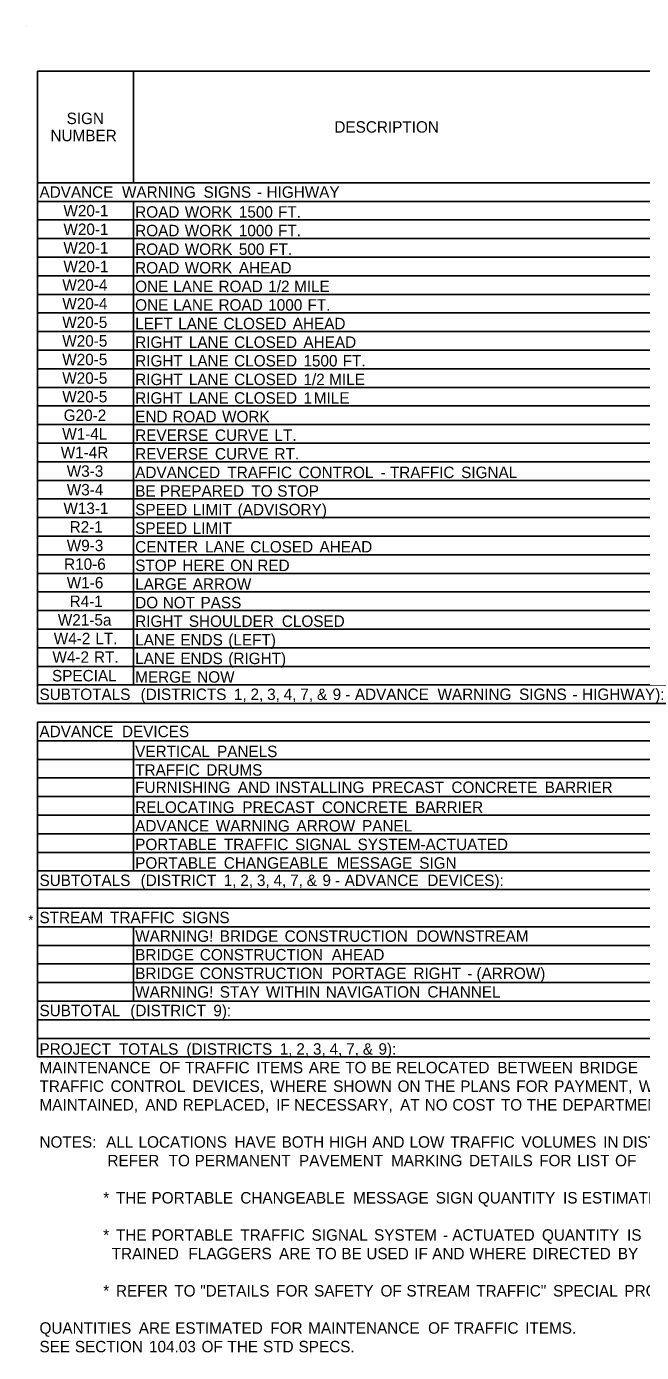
# Model space of a CAD drawing. Extents: x 544255 to 1930787, y -1947044 to 596640.
# Drawn here: x 548277 to 548600, y -1946908 to -1946213 of the extents above; entities that cross this region are included whole.
import ezdxf

# ---------------------------------------------------------------- set-up
doc = ezdxf.new("R2010")
doc.units = 0
doc.layers.add('Default', color=7, linetype='Continuous')

msp = doc.modelspace()

# ---------------------------------------------------------------- linework, layer by layer
at = {"layer": 'Default'}
for p, q in [((548277.5, -1946213.05), (548277.5, -1946213.05)), ((548283.35, -1946236.45), (549393.87, -1946236.45)), ((548283.35, -1946567.95), (548283.35, -1946236.45)), ((548283.35, -1946567.95), (548283.35, -1946236.45)), ((548333.56, -1946294.95), (548333.56, -1946236.45)), ((548283.35, -1946294.95), (549393.87, -1946294.95)), ((548283.35, -1946304.7), (549393.87, -1946304.7)), ((548333.56, -1946558.2), (548333.56, -1946304.7)), ((548333.56, -1946558.2), (548333.56, -1946304.7)), ((548283.35, -1946314.45), (549393.87, -1946314.45)), ((548283.35, -1946324.2), (549393.87, -1946324.2)), ((548283.35, -1946333.95), (549393.87, -1946333.95)), ((548283.35, -1946343.7), (549393.87, -1946343.7)), ((548283.35, -1946353.45), (549393.87, -1946353.45)), ((548283.35, -1946363.2), (549393.87, -1946363.2)), ((548283.35, -1946372.95), (549393.87, -1946372.95)), ((548283.35, -1946382.7), (549393.87, -1946382.7)), ((548283.35, -1946392.45), (549393.87, -1946392.45)), ((548283.35, -1946402.2), (549393.87, -1946402.2)), ((548283.35, -1946411.95), (549393.87, -1946411.95)), ((548283.35, -1946421.7), (549393.87, -1946421.7)), ((548283.35, -1946431.45), (549393.87, -1946431.45)), ((548283.35, -1946441.2), (549393.87, -1946441.2)), ((548283.35, -1946450.95), (549393.87, -1946450.95)), ((548283.35, -1946460.7), (549393.87, -1946460.7)), ((548283.35, -1946470.45), (549393.87, -1946470.45)), ((548283.35, -1946480.2), (549393.87, -1946480.2)), ((548283.35, -1946489.95), (549393.87, -1946489.95)), ((548283.35, -1946499.7), (549393.87, -1946499.7)), ((548283.35, -1946509.45), (549393.87, -1946509.45)), ((548283.35, -1946519.2), (549393.87, -1946519.2)), ((548283.35, -1946528.95), (549393.87, -1946528.95)), ((548283.35, -1946538.7), (549393.87, -1946538.7)), ((548283.35, -1946548.45), (549393.87, -1946548.45)), ((548283.35, -1946558.2), (549393.87, -1946558.2)), ((548283.35, -1946558.2), (549393.87, -1946558.2)), ((548283.35, -1946567.95), (549393.87, -1946567.95)), ((548283.35, -1946577.7), (549393.87, -1946577.7)), ((548283.35, -1946577.7), (549393.87, -1946577.7)), ((548283.35, -1946753.2), (548283.35, -1946577.7)), ((548283.35, -1946753.2), (548283.35, -1946577.7)), ((548283.35, -1946587.45), (549393.87, -1946587.45)), ((548333.56, -1946606.95), (548333.56, -1946587.45)), ((548333.56, -1946655.7), (548333.56, -1946587.45)), ((548283.35, -1946597.2), (549393.87, -1946597.2)), ((548283.35, -1946606.95), (549393.87, -1946606.95)), ((548283.35, -1946616.7), (548333.56, -1946616.7)), ((548283.35, -1946616.7), (549393.87, -1946616.7)), ((548333.56, -1946655.7), (548333.56, -1946616.7)), ((548283.35, -1946626.45), (549393.87, -1946626.45)), ((548283.35, -1946636.2), (549393.87, -1946636.2)), ((548283.35, -1946645.95), (549393.87, -1946645.95)), ((548283.35, -1946655.7), (548809.85, -1946655.7)), ((548283.35, -1946655.7), (549393.87, -1946655.7)), ((548283.35, -1946665.45), (549393.87, -1946665.45)), ((548283.35, -1946675.2), (549393.87, -1946675.2)), ((548283.35, -1946684.95), (549393.87, -1946684.95)), ((548333.56, -1946723.95), (548333.56, -1946684.95)), ((548283.35, -1946694.7), (549393.87, -1946694.7)), ((548283.35, -1946704.45), (549393.87, -1946704.45)), ((548283.35, -1946714.2), (549393.87, -1946714.2)), ((548283.35, -1946723.95), (549393.87, -1946723.95)), ((548283.35, -1946733.7), (549393.87, -1946733.7)), ((548283.35, -1946743.45), (549393.87, -1946743.45)), ((548283.35, -1946753.2), (549393.87, -1946753.2))]:
    msp.add_line(p, q, dxfattribs=at)

# ---------------------------------------------------------------- texts
for s, height, p in [('SIGN', 6, (548298.54, -1946264.2)), ('DESCRIPTION', 6, (548439.07, -1946268.7)), ('NUMBER', 6, (548290.08, -1946273.2)), ('ADVANCE', 6, (548284.32, -1946302.83)), (' WARNING', 6, (548325.37, -1946302.83)), (' SIGNS', 6, (548368.17, -1946302.83)), (' HIGHWAY', 6, (548401.23, -1946302.83)), ('W20-1', 6, (548296.89, -1946312.58)), (' -', 6, (548396.17, -1946302.83)), ('ROAD', 6, (548334.54, -1946313.25)), (' WORK', 6, (548358.31, -1946313.25)), (' 1500', 6, (548386.7, -1946313.25)), (' FT.', 6, (548407.27, -1946313.25)), ('W20-1', 6, (548296.89, -1946322.33)), ('ROAD', 6, (548334.54, -1946323)), (' WORK', 6, (548358.31, -1946323)), (' 1000', 6, (548386.7, -1946323)), (' FT.', 6, (548407.27, -1946323)), ('W20-1', 6, (548296.89, -1946332.08)), ('ROAD', 6, (548334.54, -1946332.75)), (' WORK', 6, (548358.31, -1946332.75)), (' 500', 6, (548386.7, -1946332.75)), (' FT.', 6, (548402.61, -1946332.75)), ('W20-1', 6, (548296.89, -1946341.83)), ('ROAD', 6, (548334.54, -1946342.5)), (' WORK', 6, (548358.31, -1946342.5)), (' AHEAD', 6, (548386.7, -1946342.5)), ('W20-4', 6, (548296.32, -1946351.58)), ('ONE', 6, (548334.54, -1946352.25)), (' LANE', 6, (548352.26, -1946352.25)), (' ROAD', 6, (548376.04, -1946352.25)), (' 1/2', 6, (548402.14, -1946352.25)), (' MILE', 6, (548415.67, -1946352.25)), ('W20-4', 6, (548296.32, -1946361.33)), ('ONE', 6, (548334.54, -1946362)), (' LANE', 6, (548352.26, -1946362)), (' ROAD', 6, (548376.04, -1946362)), (' 1000', 6, (548402.14, -1946362)), (' FT.', 6, (548422.71, -1946362)), ('W20-5', 6, (548296.28, -1946371.08)), ('LEFT', 6, (548334.54, -1946371.75)), (' LANE', 6, (548354.86, -1946371.75)), (' CLOSED', 6, (548378.64, -1946371.75)), (' AHEAD', 6, (548415, -1946371.75)), ('W20-5', 6, (548296.28, -1946380.83)), ('RIGHT', 6, (548334.54, -1946381.5)), (' LANE', 6, (548360.45, -1946381.5)), (' CLOSED', 6, (548384.23, -1946381.5)), (' AHEAD', 6, (548420.59, -1946381.5)), ('W20-5', 6, (548296.28, -1946390.58)), ('RIGHT', 6, (548334.54, -1946391.25)), (' LANE', 6, (548360.45, -1946391.25)), (' CLOSED', 6, (548384.23, -1946391.25)), (' 1500', 6, (548420.59, -1946391.25)), (' FT.', 6, (548441.15, -1946391.25)), ('W20-5', 6, (548296.28, -1946400.33)), ('RIGHT', 6, (548334.54, -1946401)), (' LANE', 6, (548360.45, -1946401)), (' CLOSED', 6, (548384.23, -1946401)), (' 1/2', 6, (548420.59, -1946401)), (' MILE', 6, (548434.12, -1946401)), ('W20-5', 6, (548296.28, -1946410.08)), ('RIGHT', 6, (548334.54, -1946410.75)), (' LANE', 6, (548360.45, -1946410.75)), (' CLOSED', 6, (548384.23, -1946410.75)), (' 1', 6, (548420.59, -1946410.75)), (' MILE', 6, (548426.03, -1946410.75)), ('G20-2', 6, (548297.03, -1946419.83)), ('END', 6, (548334.54, -1946420.5)), (' ROAD', 6, (548351.79, -1946420.5)), (' WORK', 6, (548377.89, -1946420.5)), ('W1-4L', 6, (548296.26, -1946429.58)), ('REVERSE', 6, (548334.54, -1946430.25)), (' CURVE', 6, (548374.16, -1946430.25)), (' LT.', 6, (548405.39, -1946430.25)), ('W1-4R', 6, (548295.47, -1946439.33)), ('REVERSE', 6, (548334.54, -1946440)), (' CURVE', 6, (548374.16, -1946440)), (' RT.', 6, (548405.39, -1946440)), ('W3-3', 6, (548298.63, -1946449.08)), ('ADVANCED', 6, (548334.54, -1946449.75)), (' TRAFFIC', 6, (548380.68, -1946449.75)), (' CONTROL', 6, (548418.07, -1946449.75)), (' TRAFFIC', 6, (548465.95, -1946449.75)), (' SIGNAL', 6, (548503.34, -1946449.75)), ('W3-4', 6, (548298.65, -1946458.83)), (' -', 6, (548461.09, -1946449.75)), ('BE', 6, (548334.54, -1946459.5)), (' PREPARED', 6, (548345.27, -1946459.5)), (' TO', 6, (548393.28, -1946459.5)), (' STOP', 6, (548406.88, -1946459.5)), ('W13-1', 6, (548296.89, -1946468.58)), ('SPEED', 6, (548334.54, -1946469.25)), (' LIMIT', 6, (548362.52, -1946469.25)), (' (ADVISORY)', 6, (548386.09, -1946469.25)), ('R2-1', 6, (548300.14, -1946478.33)), ('SPEED', 6, (548334.54, -1946479)), (' LIMIT', 6, (548362.52, -1946479)), ('W9-3', 6, (548298.63, -1946488.08)), ('CENTER', 6, (548334.54, -1946488.75)), (' LANE', 6, (548368.89, -1946488.75)), (' CLOSED', 6, (548392.68, -1946488.75)), (' AHEAD', 6, (548429.03, -1946488.75)), ('R10-6', 6, (548297.23, -1946497.83)), ('STOP', 6, (548334.54, -1946498.5)), (' HERE', 6, (548357, -1946498.5)), (' ON', 6, (548382.18, -1946498.5)), (' RED', 6, (548396.39, -1946498.5)), ('W1-6', 6, (548298.63, -1946507.58)), ('LARGE', 6, (548334.54, -1946508.25)), (' ARROW', 6, (548362.51, -1946508.25)), ('R4-1', 6, (548300.14, -1946517.33)), ('DO', 6, (548334.54, -1946518)), (' NOT', 6, (548346.74, -1946518)), (' PASS', 6, (548366.59, -1946518)), ('W21-5a', 6, (548293.96, -1946527.08)), ('RIGHT', 6, (548334.54, -1946527.75)), (' SHOULDER', 6, (548360.45, -1946527.75)), (' CLOSED', 6, (548409.25, -1946527.75)), ('W4-2', 6, (548291.81, -1946536.83)), (' LT.', 6, (548311.39, -1946536.83)), ('LANE', 6, (548334.54, -1946537.5)), (' ENDS', 6, (548355.99, -1946537.5)), (' (LEFT)', 6, (548381.17, -1946537.5)), ('W4-2', 6, (548291.12, -1946546.58)), (' RT.', 6, (548310.69, -1946546.58)), ('LANE', 6, (548334.54, -1946547.25)), (' ENDS', 6, (548355.99, -1946547.25)), (' (RIGHT)', 6, (548381.17, -1946547.25)), ('SPECIAL', 6, (548290.9, -1946556.33)), ('MERGE', 6, (548334.54, -1946557)), (' NOW', 6, (548364.83, -1946557)), ('SUBTOTALS', 6, (548284.32, -1946566.08)), (' (DISTRICTS', 6, (548335.15, -1946566.08)), (' 1,', 6, (548384.11, -1946566.08)), (' 2,', 6, (548392.82, -1946566.08)), (' 3,', 6, (548401.53, -1946566.08)), (' 4,', 6, (548410.24, -1946566.08)), (' 7,', 6, (548418.95, -1946566.08)), (' &', 6, (548427.67, -1946566.08)), (' 9', 6, (548435.91, -1946566.08)), (' -', 6, (548442.51, -1946566.08)), (' ADVANCE', 6, (548447.57, -1946566.08)), (' WARNING', 6, (548490.94, -1946566.08)), (' SIGNS', 6, (548533.74, -1946566.08)), (' -', 6, (548561.75, -1946566.08)), (' HIGHWAY):', 6, (548566.8, -1946566.08)), ('ADVANCE', 6, (548284.32, -1946585.58)), (' DEVICES', 6, (548325.37, -1946585.58)), ('VERTICAL', 6, (548334.54, -1946596)), (' PANELS', 6, (548375.24, -1946596)), ('TRAFFIC', 6, (548334.54, -1946605.75)), (' DRUMS', 6, (548369.6, -1946605.75)), ('FURNISHING', 6, (548334.54, -1946614.83)), (' AND', 6, (548386.18, -1946614.83)), (' INSTALLING', 6, (548405.76, -1946614.83)), (' PRECAST', 6, (548456.48, -1946614.83)), (' CONCRETE', 6, (548498.24, -1946614.83)), (' BARRIER', 6, (548547.17, -1946614.83)), ('RELOCATING', 6, (548334.54, -1946625.25)), (' PRECAST', 6, (548388.51, -1946625.25)), (' CONCRETE', 6, (548430.28, -1946625.25)), (' BARRIER', 6, (548479.2, -1946625.25)), ('ADVANCE', 6, (548334.54, -1946635)), (' WARNING', 6, (548374.63, -1946635)), (' ARROW', 6, (548416.95, -1946635)), (' PANEL', 6, (548451.31, -1946635)), ('PORTABLE', 6, (548334.54, -1946644.75)), (' TRAFFIC', 6, (548378.82, -1946644.75)), (' SIGNAL', 6, (548416.21, -1946644.75)), (' SYSTEM-ACTUATED', 6, (548448.99, -1946644.75)), ('PORTABLE', 6, (548334.54, -1946654.5)), (' CHANGEABLE', 6, (548378.82, -1946654.5)), (' MESSAGE', 6, (548438.01, -1946654.5)), (' SIGN', 6, (548481.36, -1946654.5)), ('SUBTOTALS', 6, (548284.32, -1946663.58)), (' (DISTRICT', 6, (548335.15, -1946663.58)), (' 1,', 6, (548378.75, -1946663.58)), (' 2,', 6, (548387.46, -1946663.58)), (' 3,', 6, (548396.17, -1946663.58)), (' 4,', 6, (548404.89, -1946663.58)), (' 7,', 6, (548413.6, -1946663.58)), (' &', 6, (548422.31, -1946663.58)), (' 9', 6, (548430.56, -1946663.58)), (' -', 6, (548437.15, -1946663.58)), (' ADVANCE', 6, (548442.21, -1946663.58)), (' DEVICES):', 6, (548485.58, -1946663.58)), ('*', 5, (548278.47, -1946683.95)), ('STREAM', 6, (548284.32, -1946683.08)), (' TRAFFIC', 6, (548319.13, -1946683.08)), (' SIGNS', 6, (548356.88, -1946683.08)), ('WARNING!', 6, (548334.54, -1946692.83)), (' BRIDGE', 6, (548376.69, -1946692.83)), (' CONSTRUCTION', 6, (548410.72, -1946692.83)), (' DOWNSTREAM', 6, (548479.89, -1946692.83)), ('BRIDGE', 6, (548334.54, -1946702.58)), (' CONSTRUCTION', 6, (548366.23, -1946702.58)), (' AHEAD', 6, (548435.41, -1946702.58)), ('BRIDGE', 6, (548334.54, -1946712.33)), (' CONSTRUCTION', 6, (548366.23, -1946712.33)), (' PORTAGE', 6, (548435.41, -1946712.33)), (' RIGHT', 6, (548478.29, -1946712.33)), (' -', 6, (548506.53, -1946712.33)), (' (ARROW)', 6, (548511.39, -1946712.33)), ('WARNING!', 6, (548334.54, -1946722.08)), (' STAY', 6, (548376.69, -1946722.08)), (' WITHIN', 6, (548400.86, -1946722.08)), (' NAVIGATION', 6, (548432.3, -1946722.08)), (' CHANNEL', 6, (548485.65, -1946722.08)), ('SUBTOTAL', 6, (548284.32, -1946731.83)), (' (DISTRICT', 6, (548329.72, -1946731.83)), (' 9):', 6, (548373.32, -1946731.83)), ('PROJECT', 6, (548284.32, -1946752)), (' TOTALS', 6, (548323.75, -1946752)), (' (DISTRICTS', 6, (548359.2, -1946752)), (' 1,', 6, (548408.16, -1946752)), (' 2,', 6, (548416.87, -1946752)), (' 3,', 6, (548425.58, -1946752)), (' 4,', 6, (548434.29, -1946752)), (' 7,', 6, (548443, -1946752)), (' &', 6, (548451.72, -1946752)), (' 9):', 6, (548459.96, -1946752)), ('MAINTENANCE', 6, (548284.32, -1946761.75)), (' OF', 6, (548344.9, -1946761.75)), (' TRAFFIC', 6, (548358.49, -1946761.75)), (' ITEMS', 6, (548395.88, -1946761.75)), (' ARE', 6, (548423.39, -1946761.75)), (' TO', 6, (548442.51, -1946761.75)), (' BE', 6, (548456.1, -1946761.75)), (' RELOCATED', 6, (548469.17, -1946761.75)), (' BETWEEN', 6, (548522.29, -1946761.75)), (' BRIDGE', 6, (548565.4, -1946761.75)), ('TRAFFIC', 6, (548284.32, -1946771.5)), (' CONTROL', 6, (548319.39, -1946771.5)), (' DEVICES,', 6, (548362.41, -1946771.5)), (' WHERE', 6, (548403.13, -1946771.5)), (' SHOWN', 6, (548436.21, -1946771.5)), (' ON', 6, (548469.99, -1946771.5)), (' THE', 6, (548484.21, -1946771.5)), (' PLANS', 6, (548502.86, -1946771.5)), (' FOR', 6, (548532.24, -1946771.5)), (' PAYMENT,', 6, (548552.15, -1946771.5)), (' WILL', 6, (548596.59, -1946771.5)), ('MAINTAINED,', 6, (548284.32, -1946781.25)), (' AND', 6, (548337.61, -1946781.25)), (' REPLACED,', 6, (548357.19, -1946781.25)), (' IF', 6, (548406.3, -1946781.25)), (' NECESSARY,', 6, (548415.69, -1946781.25)), (' AT', 6, (548471.33, -1946781.25)), (' NO', 6, (548484.2, -1946781.25)), (' COST', 6, (548498.73, -1946781.25)), (' TO', 6, (548524.18, -1946781.25)), (' THE', 6, (548537.77, -1946781.25)), (' DEPARTMENT.', 6, (548556.42, -1946781.25)), ('NOTES:', 6, (548284.32, -1946800.75)), ('  ALL', 6, (548314.8, -1946800.75)), (' LOCATIONS', 6, (548334.08, -1946800.75)), (' HAVE', 6, (548384.41, -1946800.75)), (' BOTH', 6, (548409.13, -1946800.75)), (' HIGH', 6, (548434.07, -1946800.75)), (' AND', 6, (548456.68, -1946800.75)), (' LOW', 6, (548476.26, -1946800.75)), (' TRAFFIC', 6, (548497.58, -1946800.75)), (' VOLUMES', 6, (548534.98, -1946800.75)), (' IN', 6, (548577.86, -1946800.75)), (' DISTRICTS', 6, (548587.89, -1946800.75)), ('                REFER', 6, (548284.32, -1946810.5)), (' TO', 6, (548349.87, -1946810.5)), (' PERMANENT', 6, (548363.47, -1946810.5)), (' PAVEMENT', 6, (548418.27, -1946810.5)), (' MARKING', 6, (548466.55, -1946810.5)), (' DETAILS', 6, (548507.48, -1946810.5)), (' FOR', 6, (548544.31, -1946810.5)), (' LIST', 6, (548564.23, -1946810.5)), (' OF', 6, (548584.09, -1946810.5)), ('               *', 6, (548284.32, -1946830)), (' THE', 6, (548322.21, -1946830)), (' PORTABLE', 6, (548340.86, -1946830)), (' CHANGEABLE', 6, (548387.47, -1946830)), (' MESSAGE', 6, (548446.66, -1946830)), (' SIGN', 6, (548490.01, -1946830)), (' QUANTITY', 6, (548512.15, -1946830)), (' IS', 6, (548556.8, -1946830)), (' ESTIMATED', 6, (548566.61, -1946830)), ('               *', 6, (548284.32, -1946849.5)), (' THE', 6, (548322.21, -1946849.5)), (' PORTABLE', 6, (548340.86, -1946849.5)), (' TRAFFIC', 6, (548387.47, -1946849.5)), (' SIGNAL', 6, (548424.86, -1946849.5)), (' SYSTEM', 6, (548457.64, -1946849.5)), (' -', 6, (548493.81, -1946849.5)), (' ACTUATED', 6, (548498.67, -1946849.5)), (' QUANTITY', 6, (548545.74, -1946849.5)), (' IS', 6, (548590.39, -1946849.5)), ('                 TRAINED', 6, (548284.32, -1946859.25)), (' FLAGGERS', 6, (548360.25, -1946859.25)), (' ARE', 6, (548407.8, -1946859.25)), (' TO', 6, (548426.92, -1946859.25)), (' BE', 6, (548440.51, -1946859.25)), (' USED', 6, (548453.58, -1946859.25)), (' IF', 6, (548478.75, -1946859.25)), (' AND', 6, (548488.15, -1946859.25)), (' WHERE', 6, (548507.73, -1946859.25)), (' DIRECTED', 6, (548540.81, -1946859.25)), (' BY', 6, (548585.55, -1946859.25)), ('               *', 6, (548284.32, -1946878.75)), (' REFER', 6, (548322.21, -1946878.75)), (' TO', 6, (548352.84, -1946878.75)), (' "DETAILS', 6, (548366.44, -1946878.75)), (' FOR', 6, (548406.24, -1946878.75)), (' SAFETY', 6, (548426.16, -1946878.75)), (' OF', 6, (548461.04, -1946878.75)), (' STREAM', 6, (548474.62, -1946878.75)), (' TRAFFIC"', 6, (548511.26, -1946878.75)), (' SPECIAL', 6, (548551.57, -1946878.75)), (' PROVISION.', 6, (548589.01, -1946878.75)), ('QUANTITIES', 6, (548284.32, -1946898.25)), (' ARE', 6, (548334.19, -1946898.25)), (' ESTIMATED', 6, (548353.31, -1946898.25)), (' FOR', 6, (548403.18, -1946898.25)), (' MAINTENANCE', 6, (548423.09, -1946898.25)), (' OF', 6, (548485.99, -1946898.25)), (' TRAFFIC', 6, (548499.58, -1946898.25)), (' ITEMS.', 6, (548536.97, -1946898.25)), ('SEE', 6, (548284.32, -1946908)), (' SECTION', 6, (548300.65, -1946908)), (' 104.03', 6, (548339.56, -1946908)), (' OF', 6, (548367.14, -1946908)), (' THE', 6, (548380.73, -1946908)), (' STD', 6, (548399.38, -1946908)), (' SPECS.', 6, (548418.03, -1946908))]:
    msp.add_text(s, height=height, dxfattribs=at).set_placement(p)

doc.saveas('drawing.dxf')
